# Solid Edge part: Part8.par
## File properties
Author: Sham
Template: ansi part.par
Last saved by: TIET
Revision: 5
Application: Solid Edge
Accuracy: 0.990
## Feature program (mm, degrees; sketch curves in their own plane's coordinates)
sketch for "unnamed Protrusion 1" plane through (0, 0, 0) normal (0, 0, 1) x-axis (1, 0, 0)
  line (0, 0) -> (114.3, 0)
  line (114.3, 0) -> (114.3, 63.5)
  line (114.3, 63.5) -> (0, 63.5)
  line (0, 63.5) -> (0, 0)
extrude "unnamed Protrusion 1" add finite 47.752 symmetric
sketch for "ExtrudedCutout_1" plane through (0, 31.75, 0) normal (0, -1, 0) x-axis (1, 0, 0)
  line (100.076, 23.876) -> (114.3, 0)
extrude "ExtrudedCutout_1" cut finite 160.7839 symmetric
sketch for "ExtrudedCutout_2" #1 plane through (114.3, 31.75, -11.938) normal (1, 0, 0) x-axis (0, 0, -1)
  line (-35.814, 23.876) -> (-20.066, 23.876)
  line (-20.066, 23.876) -> (-20.066, 31.75)
  line (-20.066, 31.75) -> (-35.814, 31.75)
  line (-35.814, 31.75) -> (-35.814, 23.876)
sketch for "ExtrudedCutout_2" #2 plane through (114.3, 31.75, -11.938) normal (1, 0, 0) x-axis (0, 0, -1)
  line (-35.814, -23.876) -> (-20.066, -23.876)
  line (-20.066, -23.876) -> (-20.066, -31.75)
  line (-20.066, -31.75) -> (-35.814, -31.75)
  line (-35.814, -31.75) -> (-35.814, -23.876)
extrude "ExtrudedCutout_2" cut finite 311.4615 symmetric
sketch for "ExtrudedCutout_13" plane through (39.0327, -43.5173, 10.7275) normal (0.707107, -0.707107, 0) x-axis (0, 0, 1)
  line (23.876, -73.1288) -> (8.128, -88.4254)
  line (8.128, -88.4254) -> (8.128, -78.2905)
  line (8.128, -78.2905) -> (-33.1815, -97.2168)
  line (-33.1815, -97.2168) -> (-33.1815, -114.3)
  line (-33.1815, -114.3) -> (0, -114.3)
  line (0, -114.3) -> (23.876, -93.9932)
  line (23.876, -93.9932) -> (23.876, -73.1288)
extrude "ExtrudedCutout_13" cut finite 140.5799 along +normal
sketch used by "ExtrudedCutout_15" plane through (0, 0, 0) normal (0, 0, 1) x-axis (1, 0, 0)
extrude "ExtrudedCutout_15" cut finite 63.2495 symmetric
sketch for "unnamed Cutout 1" plane through (0, 31.75, 0) normal (0, -1, 0) x-axis (1, 0, 0)
extrude "unnamed Cutout 1" cut finite 316.7054 symmetric
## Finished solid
Body 1: solid body, 12 faces, 30 edges, 20 vertices.
  Faces by surface: plane 12
  Edges by curve: line 30
Bounding box of the edges (mm): 100.076 x 63.500 x 47.752, from (0, 0, -23.876) to (100.076, 63.5, 23.876).
Planar faces by outward normal: +y 2, +z 3, -x 1, -y 2, -z 1, oblique 3
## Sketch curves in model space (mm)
line (114.3, 31.75, 0) -> (99.9409, 17.3909, 23.876)
line (99.9409, 17.3909, 23.876) -> (85.1876, 2.6376, 23.876)
line (85.1876, 2.6376, 23.876) -> (96.0039, 13.4539, 8.128)
line (96.0039, 13.4539, 8.128) -> (88.8374, 6.2874, 8.128)
line (88.8374, 6.2874, 8.128) -> (102.2204, 19.6704, -33.1815)
line (102.2204, 19.6704, -33.1815) -> (114.3, 31.75, -33.1815)
line (114.3, 31.75, -33.1815) -> (114.3, 31.75, 0)
line (125.6727, 0, 2.0896) -> (96.1202, 0, -32.8361)
line (100.076, 31.75, 0) -> (63.2905, 68.5355, 0)
line (100.076, 31.75, 0) -> (63.2905, -5.0355, 0)
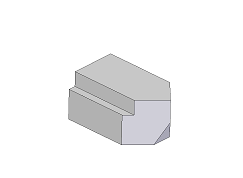
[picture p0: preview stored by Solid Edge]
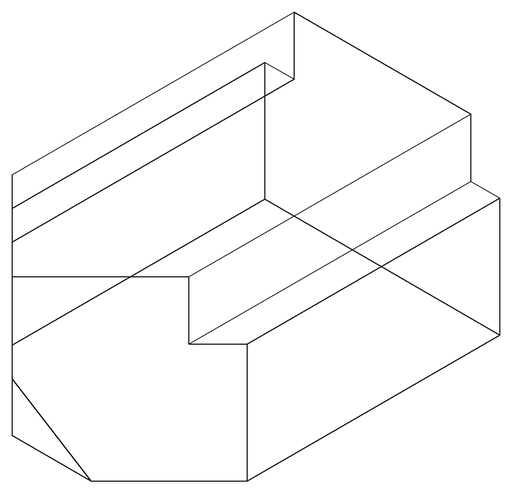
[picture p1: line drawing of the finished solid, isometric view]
